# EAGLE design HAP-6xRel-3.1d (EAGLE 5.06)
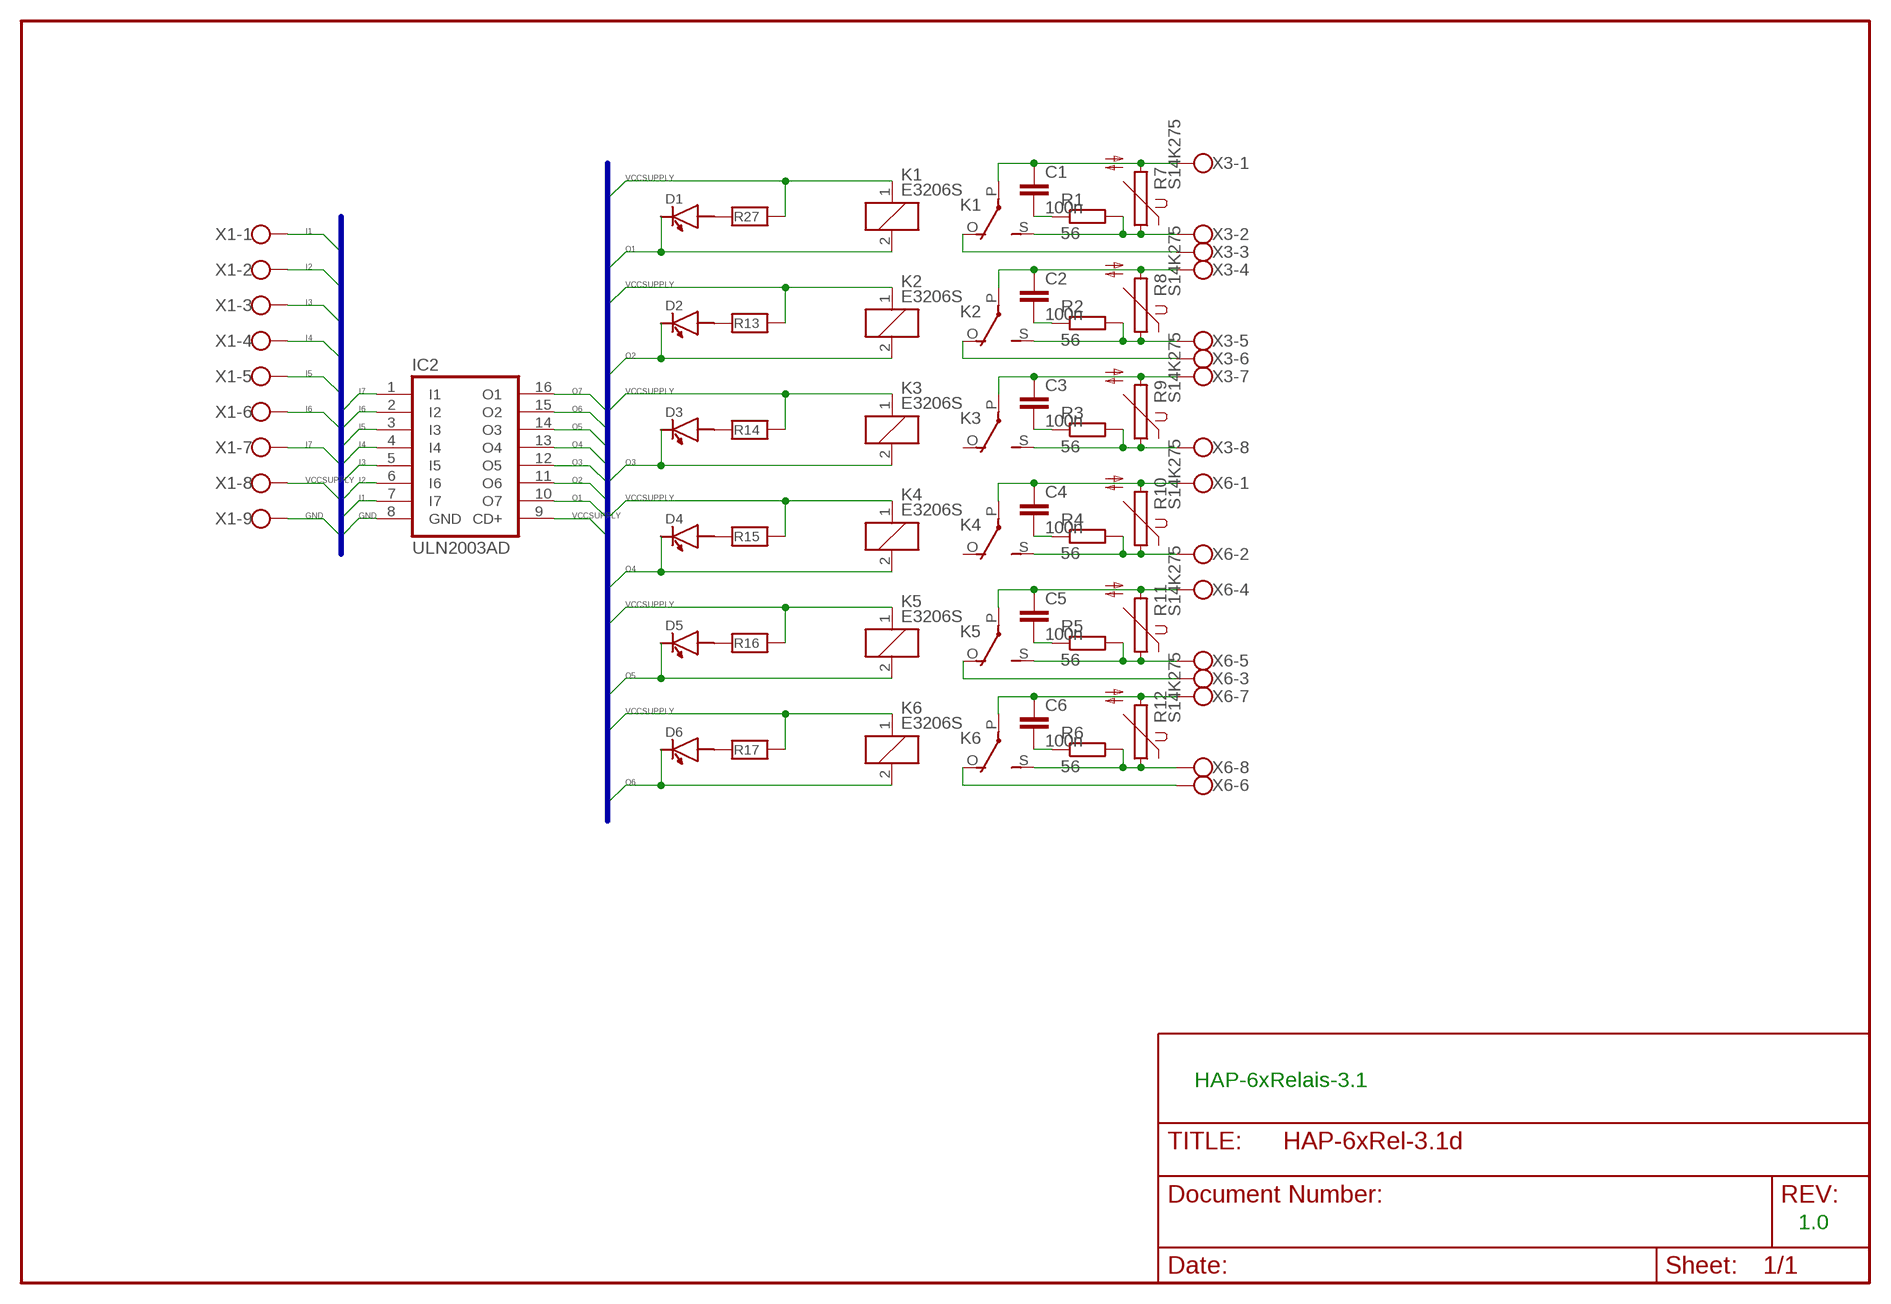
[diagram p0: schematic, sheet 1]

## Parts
C1  100n  C15/8  [C15B8]
C2  100n  C15/8  [C15B8]
C3  100n  C15/8  [C15B8]
C4  100n  C15/8  [C15B8]
C5  100n  C15/8  [C15B8]
C6  100n  C15/8  [C15B8]
D1  LED  [D0805]
D2  LED  [D0805]
D3  LED  [D0805]
D4  LED  [D0805]
D5  LED  [D0805]
D6  LED  [D0805]
IC2  ULN2003AD  [SO16]
K1  E3206S  [E3206S]
K2  E3206S  [E3206S]
K3  E3206S  [E3206S]
K4  E3206S  [E3206S]
K5  E3206S  [E3206S]
K6  E3206S  [E3206S]
R1  56  R-EU_0207/5V  [0207/5V]
R2  56  R-EU_0207/5V  [0207/5V]
R3  56  R-EU_0207/5V  [0207/5V]
R4  56  R-EU_0207/5V  [0207/5V]
R5  56  R-EU_0207/5V  [0207/5V]
R6  56  R-EU_0207/5V  [0207/5V]
R7  S14K275  [S14K275]
R8  S14K275  [S14K275]
R9  S14K275  [S14K275]
R10  S14K275  [S14K275]
R11  S14K275  [S14K275]
R12  S14K275  [S14K275]
R13  R0805  [0805]
R14  R0805  [0805]
R15  R0805  [0805]
R16  R0805  [0805]
R17  R0805  [0805]
R27  R0805  [0805]
X1  W237-09P  [W237-9P]
X3  W237-08P  [W237-8P]
X6  W237-08P  [W237-8P]

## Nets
GND [Medium]: IC2.8(GND) X1.9
I1: IC2.7(I7) X1.1
I2: IC2.6(I6) X1.2
I3: IC2.5(I5) X1.3
I4: IC2.4(I4) X1.4
I5: IC2.3(I3) X1.5
I6: IC2.2(I2) X1.6
I7: IC2.1(I1) X1.7
N$1 [Medium]: C2.2 R2.1
N$2: K1.O(2:O) X3.3
N$3: K2.O(2:O) X3.6
N$4: K6.O(2:O) X6.6
N$5: K5.O(2:O) X6.3
N$14 [Medium]: C1.2 R1.1
N$15 [Medium]: C3.2 R3.1
N$16 [Medium]: C6.2 R6.1
N$17 [Mains]: K1.S(2:S) R1.2 R7.1 X3.2
N$18 [Medium]: C5.2 R5.1
N$19 [Medium]: C4.2 R4.1
N$20 [Mains]: C2.1 K2.P(2:P) R8.2 X3.4
N$21 [Mains]: C4.1 K4.P(2:P) R10.2 X6.1
N$22 [Mains]: C3.1 K3.P(2:P) R9.2 X3.7
N$23 [Mains]: C5.1 K5.P(2:P) R11.2 X6.4
N$24 [Mains]: C6.1 K6.P(2:P) R12.2 X6.7
N$27 [Mains]: K3.S(2:S) R3.2 R9.1 X3.8
N$28 [Mains]: K2.S(2:S) R2.2 R8.1 X3.5
N$29 [Mains]: K4.S(2:S) R4.2 R10.1 X6.2
N$30 [Mains]: K6.S(2:S) R6.2 R12.1 X6.8
N$31 [Mains]: K5.S(2:S) R5.2 R11.1 X6.5
N$32 [Mains]: C1.1 K1.P(2:P) R7.2 X3.1
N$37: D1.A R27.1
N$38: D2.A R13.1
N$39: D3.A R14.1
N$40: D4.A R15.1
N$41: D5.A R16.1
N$42: D6.A R17.1
O1: D1.K IC2.10(O7) K1.2
O2: D2.K IC2.11(O6) K2.2
O3: D3.K IC2.12(O5) K3.2
O4: D4.K IC2.13(O4) K4.2
O5: D5.K IC2.14(O3) K5.2
O6: D6.K IC2.15(O2) K6.2
O7: IC2.16(O1)
VCCSUPPLY [Medium]: IC2.9(CD+) K1.1 K2.1 K3.1 K4.1 K5.1 K6.1 R13.2 R14.2 R15.2 R16.2 R17.2 R27.2 X1.8
Unconnected: K3.O(2:O) K4.O(2:O)

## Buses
VCCSUPPLY,GND,O1,O2,O3,O4,O5,O6,O7,O8,I1,I2,I3,I4,I5,I6,I7,I8

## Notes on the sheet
- HAP-6xRelais-3.1
- 1.0

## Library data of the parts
C1-C6 = capacitor-wima:C: CAPACITOR
D1-D6 = OWN:LED
IC2 = uln-udn:ULN2003A: DRIVER ARRAY
K1-K6 = relay:E3206S: RELAY 1 x switch, Eichhoff/distributor Schukat
R1-R6 = resistor:R-EU_: RESISTOR, European symbol
R7-R12 = varistor:S14K275: VARISTOR
R13-R17 R27 = OWN:R0805
X1 = con-wago-508:W237-09P: WAGO SREW CLAMP
X3 X6 = con-wago-508:W237-08P: WAGO SREW CLAMP

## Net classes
1 Mains: width 3.251 mm, clearance 0.762 mm
2 Medium: width 1.016 mm, clearance 0.254 mm

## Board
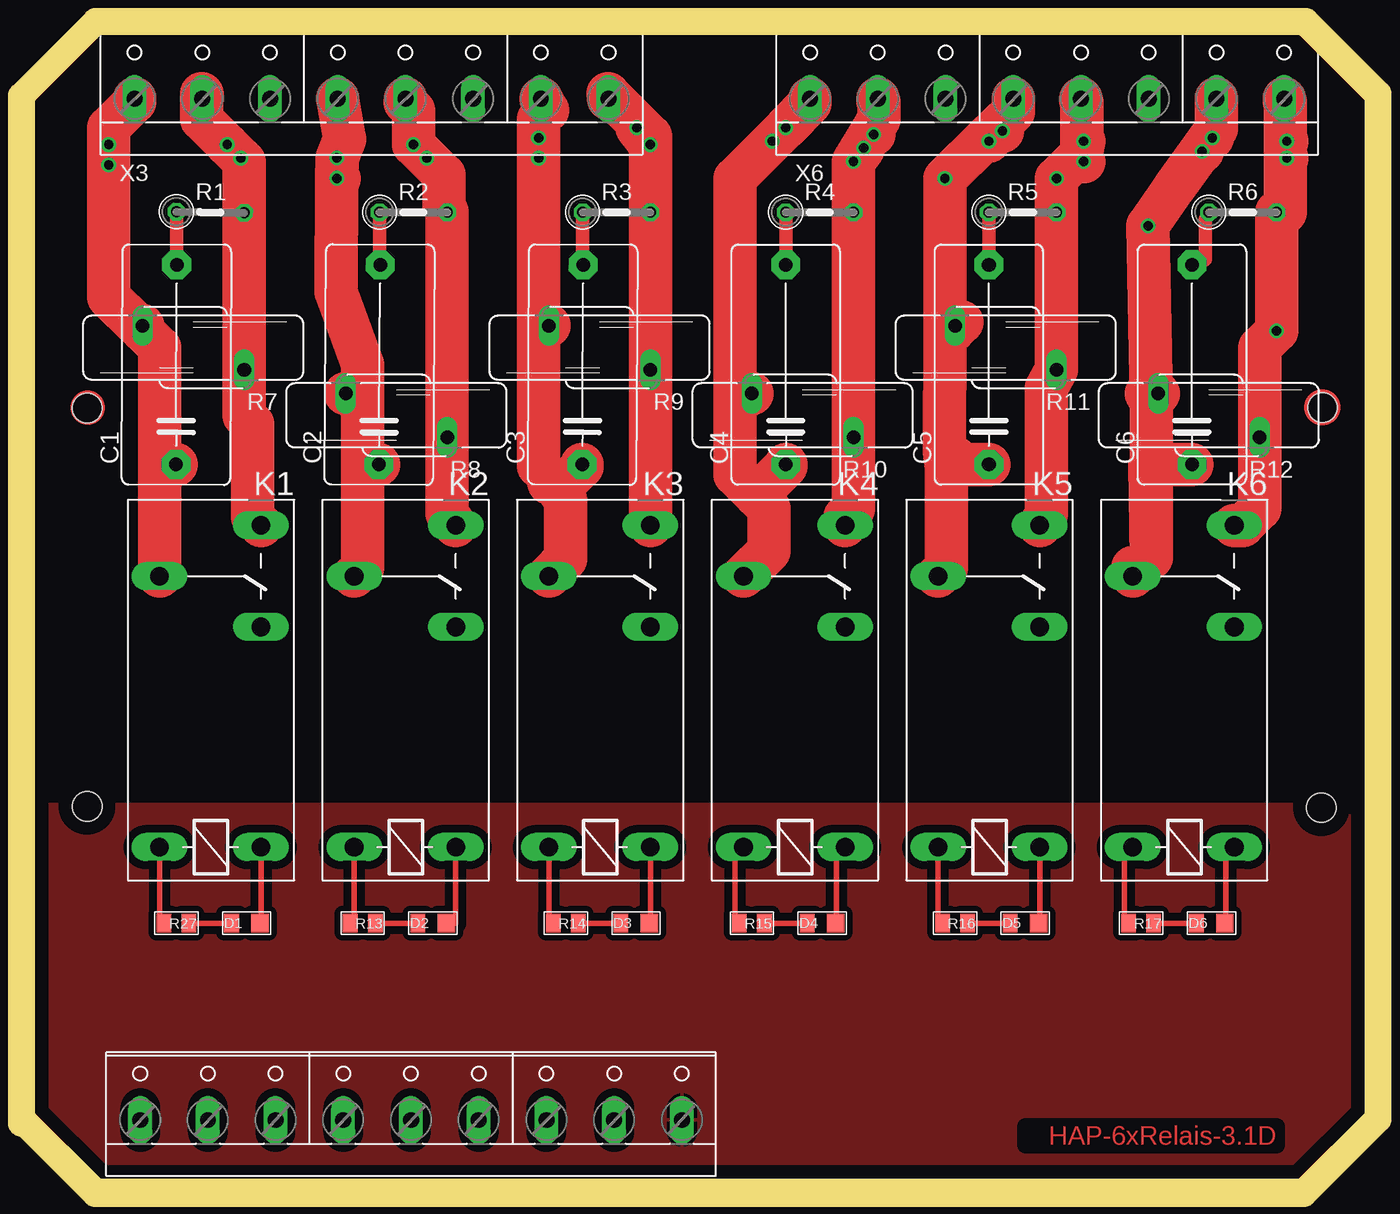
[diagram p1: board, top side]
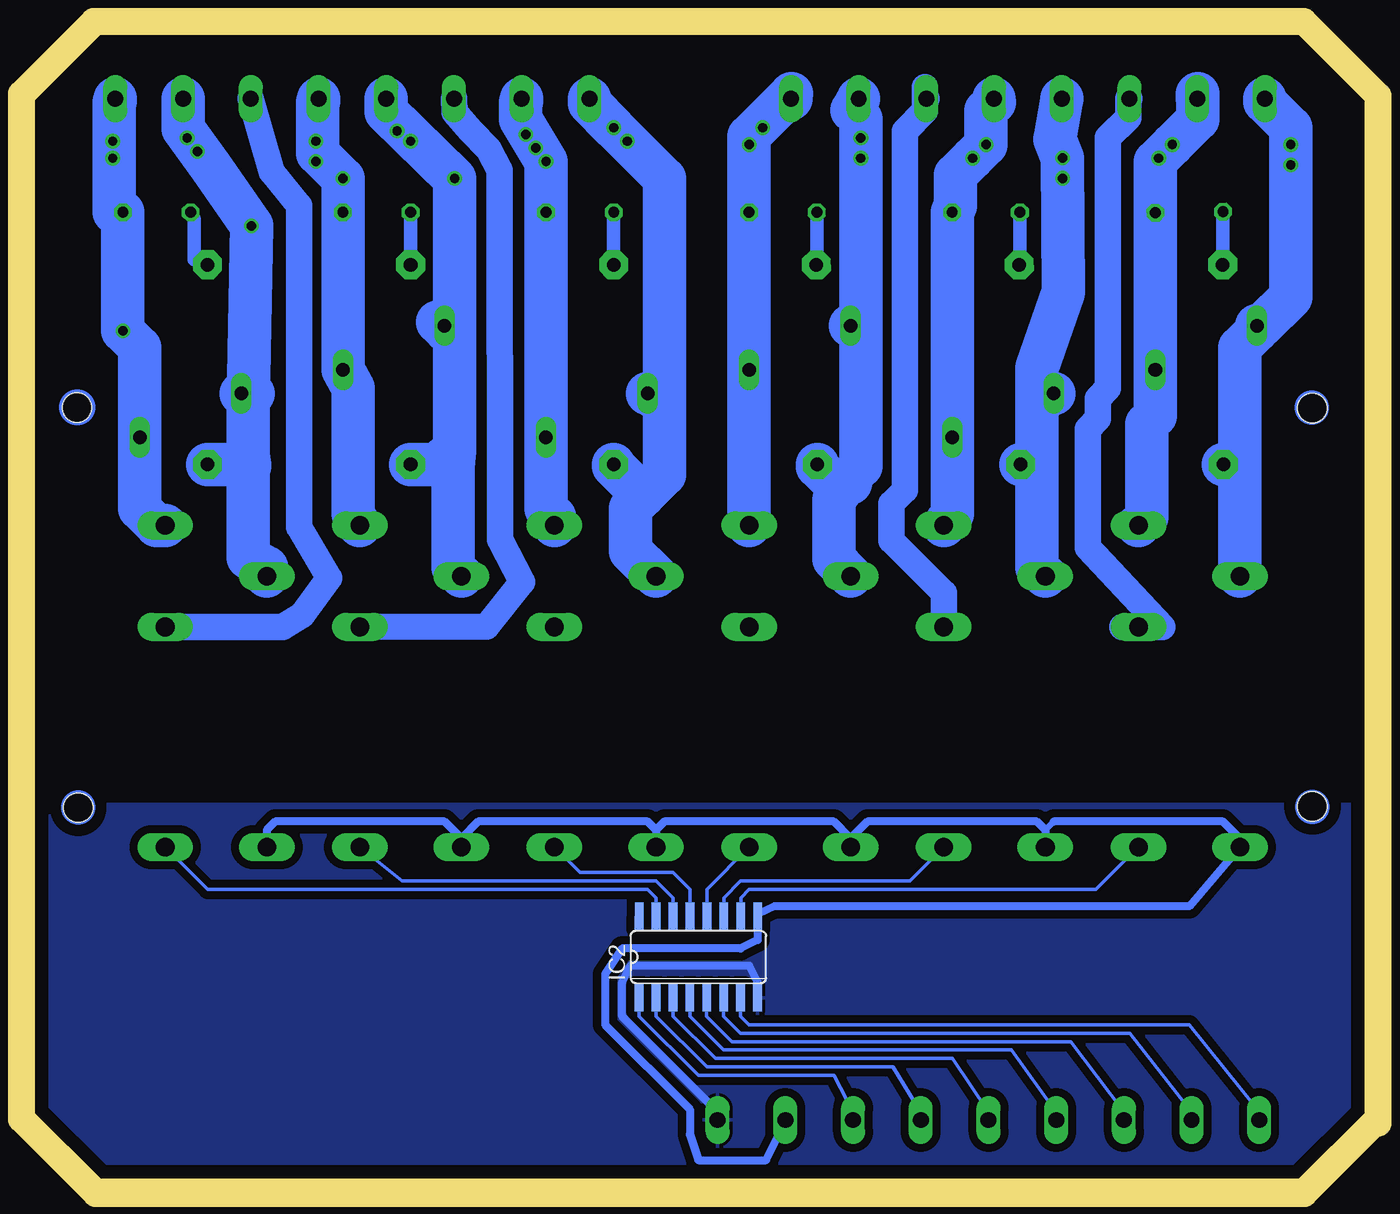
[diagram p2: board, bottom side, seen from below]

Size 100.01 x 86.08 mm. Coordinates in mm from the lower left corner, seen from the top.
Outline: 100.01,5.01 100.01,81.08 95.01,86.08 5.01,86.08 0,81.07 0.01,5 5.01,0 95,0 100,5
Copper layers (1*16): Top 0.035mm / dielectric 1.5mm / Bottom 0.035mm
Design rules "default": minimum track width 10mil, minimum drill 24mil, track to track 8mil, track to pad 12mil, pad to pad 8mil, via to via 8mil, smd to smd 8mil, copper to edge 40mil, drill to drill 8mil, minimum pad ring 10mil, minimum via ring 8mil, stop-mask expansion 4mil, vias tented up to drill 0mil, thermal gap 10mil
Holes 2.2 mm at 4.04,28.07 96.64,27.97 4.04,57.96 96.74,58
Milling: 8 lines

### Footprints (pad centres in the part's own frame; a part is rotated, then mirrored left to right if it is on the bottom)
C15B8 = drill 1.016 pad 2.159 octagon: 1 -7.493,0; 2 7.493,0
D0805 = smd 1.1 x 1.4: A -0.94,0 | smd 1.3 x 1.4: K 1.194,0
SO16 = smd 0.66 x 2.032: 1 -4.445,-3.073; 2 -3.175,-3.073; 3 -1.905,-3.073; 4 -0.635,-3.073; 5 0.635,-3.073; 6 1.905,-3.073; 7 3.175,-3.073; 8 4.445,-3.073; 9 4.445,3.073; 10 3.175,3.073; 11 1.905,3.073; 12 0.635,3.073; 13 -0.635,3.073; 14 -1.905,3.073; 15 -3.175,3.073; 16 -4.445,3.073
E3206S = drill 1.397 long: 1 -3.175,3.81; 2 -3.175,-3.81; O 13.335,-3.81; P 17.145,3.81; S 20.955,-3.81
0207/5V = drill 0.813 octagon: 1 -2.54,0; 2 2.54,0
S14K275 = drill 1.016 long: 1 -1.651,-3.81; 2 1.651,3.81
0805 = smd 1.092 x 1.397: 1 -0.94,0; 2 0.94,0
W237-9P = drill 1.194 long: 1 -20.32,-0.635; 2 -15.24,-0.635; 3 -10.16,-0.635; 4 -5.08,-0.635; 5 0,-0.635; 6 5.08,-0.635; 7 10.16,-0.635; 8 15.24,-0.635; 9 20.32,-0.635
W237-8P = drill 1.194 long: 1 -17.78,-0.635; 2 -12.7,-0.635; 3 -7.62,-0.635; 4 -2.54,-0.635; 5 2.54,-0.635; 6 7.62,-0.635; 7 12.7,-0.635; 8 17.78,-0.635

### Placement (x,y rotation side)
C1  10.74,61.22 89.8 top
C2  25.98,61.22 89.6 top
C3  41.22,61.22 89.7 top
C4  56.46,61.22 90 top
C5  71.7,61.22 90 top
C6  86.94,61.22 90 top
D1  15.82,19.31 0 top
D2  29.79,19.31 0 top
D3  45.03,19.31 0 top
D4  59,19.31 0 top
D5  74.24,19.31 0 top
D6  88.21,19.31 0 top
IC2  50.11,16.77 359.9 bottom
K1  13.28,28.2 90 top
K2  27.88,28.2 90 top
K3  42.49,28.2 90 top
K4  57.09,28.2 90 top
K5  71.7,28.2 90 top
K6  86.31,28.2 90 top
R1  13.28,72.65 359.1 top
R2  28.52,72.65 0 top
R3  43.76,72.65 0 top
R4  59,72.65 0 top
R5  74.24,72.65 0 top
R6  90.75,72.65 0 top
R7  12.01,62.49 90 top
R8  27.25,57.41 90 top
R9  42.49,62.49 90 top
R10  57.73,57.41 90 top
R11  72.97,62.49 90 top
R12  88.21,57.41 90 top
R13  24.71,19.31 180 top
R14  39.95,19.31 180 top
R15  53.92,19.31 180 top
R16  69.16,19.31 180 top
R17  83.13,19.31 180 top
R27  10.74,19.31 180 top
X1  28.34,5.17 0 top
X3  25.38,81.81 0 top
X6  76.07,81.81 0 top

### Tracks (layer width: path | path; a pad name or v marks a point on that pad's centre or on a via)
GND
  Bottom 0.406: X1.9 48.67,5.17
  Bottom 0.61: IC2.8 45.67,14.87 46.3,16.13 55.19,16.13 55.82,14.87 55.82,12.33 48.67,5.17
  pour Bottom (isolate 0.61): 0.58,28.2 99.64,28.2 100.28,27.57 100.28,4.71 95.2,-0.38 5.03,-0.38 -0.05,4.71 -0.05,28.2
  pour Top (isolate 0.61): 0.58,28.2 99.64,28.2 100.28,27.57 100.28,4.71 95.2,-0.38 5.03,-0.38 -0.05,4.71 -0.05,28.2
I1
  Bottom 0.254: IC2.7 46.94,12.33 46.3,11.69 13.28,11.69 8.03,5.17 X1.1
I2
  Bottom 0.254: IC2.6 48.21,12.33 46.94,11.05 17.72,11.05 13.11,5.17 X1.2
I3
  Bottom 0.254: IC2.5 49.48,12.33 47.57,10.42 22.17,10.42 18.19,5.17 X1.3
I4
  Bottom 0.254: IC2.4 50.75,12.33 48.2,9.79 26.61,9.79 23.27,5.17 X1.4
I5
  Bottom 0.254: IC2.3 52.02,12.33 48.84,9.15 31.06,9.15 28.35,5.17 X1.5
I6
  Bottom 0.254: IC2.2 53.29,12.33 49.48,8.52 35.51,8.52 33.43,5.17 X1.6
I7
  Bottom 0.254: IC2.1 54.56,12.33 50.11,7.88 39.95,7.88 38.51,5.17 X1.7
N$1
  Top 1.016: R2.1 25.98,69.6 C2.2
N$2
  Bottom 2: X3.3 17.85,81.18 17.85,79.76 19.38,78.24 19.38,59.44 20.14,58.68 20.14,57.16 20.9,56.39 20.9,47.5 15.3,41.51 K1.O 18.29,41.54
N$3
  Bottom 2: K2.O 31.7,44.08 35.63,48.01 35.63,50.81 34.62,51.82 34.62,78.75 33.09,80.27 33.09,81.27 | 33.09,81.27 33.09,82.05 | 33.09,81.27 X3.6
N$4
  Bottom 2: X6.6 82.11,75.7 80.08,73.16 80.08,49.03 77.8,45.22 79.83,42.42 81.3,41.52 K6.O
N$5
  Bottom 2: K5.O 66.01,41.56 63.35,44.89 65,48.09 65.04,75.82 65.84,77.38 67.19,78.77 68.41,80.17 X6.3
N$14
  Top 1.016: R1.1 10.74,72.14 10.74,69.6 C1.2
N$15
  Top 1.016: R3.1 41.22,69.6 C3.2
N$16
  Top 1.016: R6.1 87.96,72.14 87.96,69.09 C6.2
N$17  (via drill 0.7)
  Top 3.251: 15.82,60.59 R7.1 15.82,57.41 16.45,56.77 16.45,49.79 K1.S | 15.82,60.59 R1.2 15.82,76.46 v15.57,76.71 v14.55,77.73 12.64,79.63 12.64,81.54 12.68,81.5 X3.2 | 15.82,60.59
  Bottom 3.251: 15.82,60.59 R7.1 15.82,57.41 16.45,56.77 16.45,49.79 K1.S | 15.82,60.59 R1.2 15.82,76.46 v14.55,77.73 12.64,79.63 12.64,81.54 12.68,81.5 X3.2 | 15.82,60.59
N$18
  Top 1.016: C5.2 R5.1
N$19
  Top 1.016: C4.2 R4.1
N$20  (via drill 0.7)
  Top 3.251: 22.77,75.19 22.71,66.65 24.71,61.22 24.71,58.05 | 22.77,75.19 v22.78,76.73 23.35,78.15 X3.4 | 24.71,53.6 24.71,45.98 K2.P | 24.71,53.6 24.71,58.05 | R8.2 23.69,59.06 24.71,58.05 | C2.1 24.84,53.73 24.71,53.6 | v22.78,75.2 22.93,75.19 22.77,75.19
  Bottom 3.251: X3.4 23.35,78.15 v22.78,76.73 22.71,66.65 24.71,60.97 24.71,58.05 | 24.71,53.6 24.71,45.98 K2.P | 24.71,53.6 24.71,58.05 | R8.2 23.69,59.06 24.71,58.05 | C2.1 24.84,53.73 24.71,53.6
N$21  (via drill 0.7)
  Top 3.251: X6.1 58.29,80.83 v56.46,79 52.65,75.19 52.65,59.31 | 52.65,59.31 52.65,52.97 54.24,51.38 | 54.24,51.38 55.19,50.42 55.19,47.25 K4.P | C4.1 56.46,53.6 54.24,51.38 | R10.2 53.67,59.06 53.28,58.68 52.65,59.31
  Bottom 3.251: X6.1 58.29,80.83 v56.46,79 52.65,75.19 52.65,59.31 | 52.65,59.31 52.65,52.97 54.24,51.38 | 54.24,51.38 55.19,50.42 55.19,47.25 K4.P | C4.1 56.46,53.6 54.24,51.38 | R10.2 53.67,59.06 53.28,58.68 52.65,59.31
N$22  (via drill 0.7)
  Top 3.251: X3.7 38.59,80.31 37.92,79.63 v37.92,78.24 37.92,63.76 | 37.92,63.76 37.92,53.6 38.55,52.97 | 38.55,52.97 39.95,51.06 39.95,46.62 K3.P | C3.1 41.18,53.56 39.95,52.33 38.68,52.33 38.55,52.97 | R9.2 38.3,64.14 37.92,63.76
  Bottom 2: v37.92,78.24 v37.92,76.71
  Bottom 3.251: X3.7 38.59,80.31 37.92,79.63 v37.92,78.24 v37.92,76.71 37.92,63.76 | 37.92,63.76 37.92,53.6 38.55,52.97 | 38.55,52.97 39.95,51.06 39.95,46.62 K3.P | C3.1 41.18,53.56 39.95,52.33 38.68,52.33 38.55,52.97 | R9.2 38.3,64.14 37.92,63.76
N$23  (via drill 0.7)
  Top 3.251: X6.4 73.53,80.19 72.39,79.08 | 71.49,78.2 v68.4,75.19 68.4,63.76 | 71.49,78.2 72.39,79.08 | 68.38,54.76 68.4,63.76 | K5.P 68.53,45.98 68.53,53.6 68.38,54.76 | C5.1 69.29,53.73 69.16,53.6 69.16,54.23 68.38,54.76 | R11.2 69.67,64.4 69.03,63.76 68.4,63.76 | 71.49,78.2 v71.7,77.98 | 72.39,79.08 v72.72,78.75
  Bottom 3.251: X6.4 73.53,80.19 v68.4,75.19 68.4,63.76 | 68.39,54.8 68.4,63.76 | K5.P 68.53,45.98 68.53,53.6 68.39,54.8 | C5.1 69.29,53.73 69.16,53.6 69.16,54.23 68.39,54.8 | R11.2 69.67,64.4 69.03,63.76 68.4,63.76
N$24  (via drill 0.7)
  Top 3.251: X6.7 88.77,78.93 88.34,78.32 | 87.61,77.29 85.67,74.56 v83.64,71.63 83.89,58.43 | 87.61,77.29 88.34,78.32 | 83.89,46.74 83.13,45.98 82.5,45.98 K6.P | 83.89,46.74 83.89,58.43 | C6.1 83.89,53.73 83.77,53.6 83.89,46.74 | R12.2 83.51,59.06 83.89,58.43 | 87.61,77.29 v87.7,77.22 | 88.34,78.32 v88.46,78.24
  Bottom 3.251: X6.7 88.77,78.93 86.69,76.08 v83.64,71.63 83.89,58.43 | 83.89,54.36 83.89,46.74 82.5,45.98 K6.P | 83.89,54.36 83.89,58.43 | C6.1 83.89,53.73 83.77,53.6 83.89,54.36 | R12.2 83.51,59.06 83.89,58.43
N$25
  Bottom 1.016: 71.7,68.71 71.7,72.65
N$26
  Bottom 1.016: 56.46,68.71 56.46,72.65
N$27  (via drill 0.7)
  Top 3.251: K3.S R9.1 R3.2 v46.3,77.73 | 43.16,81.5 43.12,81.54 | 43.16,81.5 X3.8 | v46.3,77.73 46.3,78.37 43.16,81.5 | v46.3,77.73 v45.28,79
  Bottom 3.251: K3.S R9.1 R3.2 v46.3,77.73 46.3,78.37 43.16,81.5 | 43.16,81.5 43.12,81.54 | 43.16,81.5 X3.8
N$28  (via drill 0.7)
  Top 3.251: K2.S 31.06,50.04 R8.1 R2.2 30.81,73.16 30.81,75.44 v28.52,77.73 28.52,80.27 27.88,80.91 27.92,80.94 X3.5
  Bottom 2: v29.54,76.71 v28.52,77.73
  Bottom 3.251: K2.S 31.06,50.04 R8.1 R2.2 30.81,73.16 30.81,75.44 v29.54,76.71 v28.52,77.73 28.52,80.27 27.88,80.91 27.92,80.94 X3.5
N$29  (via drill 0.7)
  Top 3.251: X6.2 63.37,80.98 63.45,80.91 63.45,79.63 62.84,78.63 | v61.54,76.46 62.84,78.63 | v61.54,76.46 R4.2 R10.1 61.54,50.42 60.91,49.79 K4.S | v61.54,76.46 v62.3,77.48 | 62.84,78.63 v63.06,78.49
  Bottom 3.251: X6.2 63.37,80.98 63.45,80.91 63.45,79.63 v61.54,76.46 R4.2 R10.1 61.54,50.42 60.91,49.79 K4.S
N$30  (via drill 0.7)
  Top 3.251: K6.S 90.75,49.16 92.02,50.42 R12.1 | R12.1 92.02,56.14 | R12.1 92.02,62.49 v93.29,63.76 93.29,71.38 | 93.29,71.38 93.29,72.01 93.93,72.65 93.93,76.71 | X6.8 93.85,80.98 93.93,80.91 93.93,77.98 | 93.93,76.71 93.93,77.98 | 93.29,71.38 R6.2 | 93.93,76.71 v94.05,76.71 | 93.93,77.98 v94.05,77.98
  Bottom 3.251: K6.S 90.75,49.16 92.02,50.42 R12.1 | R12.1 92.02,56.14 | R12.1 92.02,62.49 v93.29,63.76 93.29,71.38 | 93.29,71.38 93.29,72.01 93.93,72.65 93.93,80.91 93.85,80.98 X6.8 | 93.29,71.38 R6.2
N$31  (via drill 0.7)
  Top 3.251: K5.S 76.02,50.04 76.02,59.44 R11.1 R5.2 v76.78,75.19 78.43,76.84 | 78.43,76.84 78.69,77.09 | X6.5 78.61,80.98 78.69,80.91 78.69,77.09 | 78.43,76.84 v78.81,76.46 | 78.69,77.09 v78.81,77.98
  Bottom 3.251: K5.S 76.02,50.04 76.02,59.44 R11.1 R5.2 v76.78,75.19 78.69,77.09 78.69,80.91 78.61,80.98 X6.5
N$32  (via drill 0.7)
  Top 3.251: 9.47,52.97 9.47,62.49 8.2,63.76 R7.2 7.82,64.14 5.66,66.3 v5.66,77.73 5.66,79 7.6,80.94 X3.1 | K1.P 9.47,52.97 | 9.47,52.97 10.11,53.6 | C1.1 10.23,53.73 9.47,52.97
  Bottom 2: v5.66,76.21 v5.66,77.73
  Bottom 3.251: 9.47,52.97 9.47,62.49 8.2,63.76 R7.2 7.82,64.14 5.66,66.3 v5.66,76.21 v5.66,77.73 5.66,79 7.6,80.94 X3.1 | K1.P 9.47,52.97 | 9.47,52.97 10.11,53.6 | C1.1 10.23,53.73 9.47,52.97
N$33
  Bottom 1.016: 25.98,72.65 25.98,69.6 26.03,68.71
N$34
  Bottom 1.016: 10.74,72.69 10.74,72.14 10.74,69.6 10.77,68.71
N$35
  Bottom 1.016: 41.22,72.65 41.22,69.6 41.26,68.71
N$36
  Bottom 1.016: 88.21,72.65 87.96,72.14 87.96,69.09 86.94,68.71
N$37
  Top 0.406: R27.1 D1.A
N$38
  Top 0.406: R13.1 D2.A
N$39
  Top 0.406: R14.1 D3.A
N$40
  Top 0.406: R15.1 D4.A
N$41
  Top 0.406: R16.1 D5.A
N$42
  Top 0.406: R17.1 D6.A
O1
  Top 0.406: D1.K 17.09,19.31 K1.2
  Bottom 0.254: IC2.10 46.93,21.22 46.3,21.85 20.27,21.85 K1.2
O2
  Top 0.406: D2.K 31.7,19.31 K2.2
  Bottom 0.254: IC2.11 48.2,21.22 46.94,22.48 34.23,22.48 K2.2
O3
  Top 0.406: D3.K 46.3,19.31 K3.2
  Bottom 0.254: IC2.12 49.47,21.86 K3.2
O4
  Top 0.406: D4.K 60.27,19.31 60.27,24.39 60.91,24.39 K4.2
  Bottom 0.254: IC2.13 50.74,21.84 52.02,23.12 59,23.12 K4.2
O5
  Top 0.406: D5.K 75.51,19.31 K5.2
  Bottom 0.254: IC2.14 52.01,21.21 53.28,22.48 72.34,22.48 K5.2
O6
  Top 0.406: D6.K 89.48,19.31 89.48,24.39 90.12,24.39 K6.2
  Bottom 0.254: K6.2 86.94,21.85 53.92,21.85 53.28,21.21 53.28,19.95 53.28,19.94 IC2.15
S$2  (via drill 0.7)
  other vias: 55.44,77.98
VCCSUPPLY
  Top 0.406: R17.2 81.86,19.31 81.86,24.39 82.5,24.39 K6.1 | R16.2 67.89,19.31 K5.1 | R15.2 52.65,19.31 52.65,24.39 53.28,24.39 K4.1 | R14.2 38.68,19.31 K3.1 | R13.2 24.07,19.31 K2.1 | R27.2 9.47,19.31 K1.1
  Bottom 0.406: 45.66,19.95 IC2.9 | 23.44,26.93 24.07,26.3 | K1.1 9.47,25.66 | 43.76,5.34 43.59,5.17 X1.8
  Bottom 0.61: IC2.9 45.66,18.05 46.94,17.41 55.82,17.41 57.09,15.5 57.09,11.69 50.74,5.34 50.74,3.44 50.11,1.53 45.03,1.53 43.76,4.07 43.76,5.34 | 45.66,19.95 44.39,20.58 13.28,20.58 K1.1 | K2.1 24.07,26.3 24.71,26.93 37.41,26.93 38.68,25.66 | 23.44,26.93 10.74,26.93 9.47,25.66 | 38.68,25.66 K3.1 | 53.28,26.3 K4.1 | 53.28,26.3 52.65,26.93 39.95,26.93 38.68,25.66 | 67.89,25.66 K5.1 | 67.89,25.66 66.62,26.93 53.92,26.93 53.28,26.3 | K6.1 82.5,26.3 81.86,26.93 69.16,26.93 67.89,25.66
(copper drawn outside any net)
  shapes: Bottom circle x4, Top circle x2

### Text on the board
Top: HAP-6xRelais-3.1D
